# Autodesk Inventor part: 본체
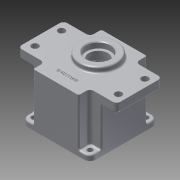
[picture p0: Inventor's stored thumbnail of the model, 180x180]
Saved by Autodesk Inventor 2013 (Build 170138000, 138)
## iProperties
Created: 2015-07
Part Number: 본체
Material: 알루미늄 6061
Document SubType Name: Modeling
Designer: user
Density: 2.71 g/cm^3
Mass: 706.146 g
Surface Area: 672.799 cm^2
Volume: 260.571 cm^3
Author: user
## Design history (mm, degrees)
sketch "스케치1"
  geometry: L1 (-65, -30)-(65, -30); L2 (65, -30)-(65, 30); L3 (65, 30)-(-65, 30); L4 (-65, 30)-(-65, -30); L5 (-65, -30)-(65, 30); L6 (65, -30)-(-65, 30); 1 further point
  constraints: 12 end point, 2 midpoint, 2 parallel, 1 horizontal, 1 perpendicular
  dimensions: "d0" = 130 distance of L3.end L2.end; "d1" = 60 distance of L2.end L1.end
extrude "돌출1" new body sketch "스케치1" distance "d2" = 12; taper "d3" = 0 deg
sketch "스케치2"
  geometry: L1 (-30, -45)-(30, -45); L2 (30, -45)-(30, 45); L3 (30, 45)-(-30, 45); L4 (-30, 45)-(-30, -45); L5 (-30, -45)-(30, 45); L6 (30, -45)-(-30, 45); 1 further point
  constraints: 12 end point, 2 midpoint, 2 parallel, 1 horizontal, 1 perpendicular
  dimensions: "d4" = 60 distance of L3.end L2.end; "d5" = 90 distance of L2.end L1.end
extrude "돌출2" join sketch "스케치2" distance "d6" = 70; taper "d7" = 0 deg
sketch "스케치3"
  geometry: L1 (-30, -45)-(30, -45) reference; L2 (30, -45)-(30, 45) reference; L3 (30, 45)-(-30, 45) reference; L4 (-30, 45)-(-30, -45) reference; L5 (-45, -45)-(45, -45); L6 (45, -45)-(45, 45); L7 (45, 45)-(-45, 45); L8 (-45, 45)-(-45, -45); L9 (-45, -45)-(45, 45); L10 (45, -45)-(-45, 45); 1 further point
  constraints: 12 end point, 2 midpoint, 2 parallel, 1 horizontal, 1 perpendicular
  dimensions: "d8" = 90 distance of L7.end L6.end; "d9" = 90 distance of L6.end L5.end
extrude "돌출3" join sketch "스케치3" distance "d10" = 7; taper "d11" = 0 deg
fillet "모깎기1" dims "d12" = 5
fillet "모깎기2" dims "d13" = 8
sketch "스케치4"
  geometry: L1 (-45, -30)-(45, -30); L2 (45, -30)-(45, 30); L3 (45, 30)-(-45, 30); L4 (-45, 30)-(-45, -30); L5 (-45, -30)-(45, 30); L6 (45, -30)-(-45, 30); 1 further point
  constraints: 12 end point, 2 midpoint, 2 parallel, 1 horizontal, 1 perpendicular
  dimensions: "d14" = 90 distance of L3.end L2.end; "d15" = 60 distance of L2.end L1.end
extrude "돌출4" join sketch "스케치4" distance "d16" = 70; taper "d17" = 0 deg
fillet "모깎기3" dims "d18" = 5
fillet "모깎기4" dims "d19" = 2
fillet "모깎기5" dims "d20" = 2
fillet "모깎기6" dims "d21" = 2
sketch "스케치5"
  geometry: L1 (-37, -37)-(37, -37); L2 (37, -37)-(37, 37); L3 (37, 37)-(-37, 37); L4 (-37, 37)-(-37, -37); L5 (-37, -37)-(37, 37); L6 (37, -37)-(-37, 37); C1 r 3.5 at (37, 37); C2 r 3.5 at (37, -37); C3 r 3.5 at (-37, 37); C4 r 3.5 at (-37, -37); 1 further point
  constraints: 12 end point, 4 centre point, 4 coincident, 2 midpoint, 2 parallel, 1 horizontal, 1 perpendicular
  dimensions: "d22" = 74 distance of L3.end L2.end; "d23" = 74 distance of L2.end L1.end; "d24" = 7 diameter of C1; "d25" = 7 diameter of C2; "d26" = 7 diameter of C3; "d27" = 7 diameter of C4
extrude "돌출5" cut sketch "스케치5" distance "d28" = 70; taper "d29" = 0 deg
sketch "스케치6"
  geometry: L1 (-55, -17.5)-(55, -17.5); L2 (55, -17.5)-(55, 17.5); L3 (55, 17.5)-(-55, 17.5); L4 (-55, 17.5)-(-55, -17.5); L5 (-55, -17.5)-(55, 17.5); L6 (55, -17.5)-(-55, 17.5); C1 r 4.5 at (55, 17.5); C2 r 4.5 at (55, -17.5); C3 r 4.5 at (-55, -17.5); C4 r 4.5 at (-55, 17.5); 1 further point
  constraints: 12 end point, 4 centre point, 4 coincident, 2 midpoint, 2 parallel, 1 horizontal, 1 perpendicular
  dimensions: "d30" = 110 distance of L3.end L2.end; "d31" = 35 distance of L2.end L1.end; "d32" = 9 diameter of C1; "d33" = 9 diameter of C2; "d34" = 9 diameter of C3; "d35" = 9 diameter of C4
extrude "돌출6" cut sketch "스케치6" distance "d36" = 20; taper "d37" = 0 deg
sketch "스케치7"
  geometry: C1 r 40 at (0, 0); 1 further point
  constraints: 1 centre point, 1 coincident
  dimensions: "d38" = 80 diameter of C1
extrude "돌출7" cut sketch "스케치7" distance "d39" = 9; taper "d40" = 0 deg
sketch "스케치8"
  geometry: C1 r 40 at (0, 0) reference; C2 r 39 at (0, 0)
  constraints: 1 centre point, 1 coincident
  dimensions: "d41" = 78 diameter of C2
extrude "돌출8" cut sketch "스케치8" distance "d42" = 52; taper "d43" = 0 deg
sketch "스케치10"
  geometry: L1 (-45, -70)-(-45, 0) reference; L2 (-45, 0)-(45, 0) reference; L3 (45, 0)-(45, -70) reference; L4 (45, -70)-(40, -70) reference; L5 (40, -70)-(40, -61) reference; L6 (40, -61)-(39, -61) reference; L7 (39, -61)-(39, -9) reference; L8 (39, -9)-(-39, -9) reference; L9 (-39, -9)-(-39, -61) reference; L10 (-39, -61)-(-40, -61) reference; L11 (-40, -61)-(-40, -70) reference; L12 (-40, -70)-(-45, -70) reference; L13 (0, 0)-(11, 0); L14 (0, 0)-(-20, 0); L15 (11, 0)-(11, -16); L16 (11, 0)-(11, 7); L17 (-20, 0)-(-20, -16); L18 (27, 7)-(36, 7); L19 (36, 7)-(36, -5); L20 (36, -5)-(31.5, -5); L21 (31.5, -5)-(31.5, -16); L22 (31.5, -16)-(28.5, -16); L23 (28.5, -16)-(28.5, -6); L24 (28.5, -6)-(23.5, -6); L25 (23.5, -6)-(23.5, -1); L26 (23.5, -1)-(27, -1); L27 (27, -1)-(27, 7); L28 (-20, -16)-(-6, -16); L29 (-6, -16)-(-6, 0); L30 (-6, 0)-(-20, 0)
  constraints: 36 end point, 7 parallel, 7 perpendicular, 3 point on line, 2 collinear
  dimensions: "d44" = 11 distance of L13.start L13.end; "d45" = 20 distance of L13.start L14.end; "d46" = 16 distance of L13.end L15.end; "d47" = 7 distance of L13.end L16.end; "d48" = 16 distance of L14.end L17.end; "d49" = 32 diameter of L27 L15; "d50" = 25 diameter of L25 L15; "d51" = 35 diameter of L23 L15; "d52" = 41 diameter of L21 L15; "d53" = 50 diameter of L19 L15; "d54" = 7 distance between parallel lines of L2 L18; "d55" = 7 distance between parallel lines of L8 L22; "d56" = 8 distance of L26.end L18.start; "d57" = 5 distance of L24.end L25.end; "d58" = 4 distance between parallel lines of L8 L20; "d59" = 14 distance of L17.end L28.end
  node "절단 모서리 투영1"
revolve "회전1" stored, may be unused: angle "d60" = 90 deg
revolve "회전2" stored, may be unused: angle "d61" = 90 deg
sketch "스케치11"
  geometry: C1 r 17.5 at (0, 0); C2 r 12.5 at (0, 0); A1 r 17.5 centre (0, 0) between (2.777, -17.278) and (-2.777, -17.278) reference; A2 r 14 centre (0, -31) between (2.777, -17.278) and (-2.777, -17.278) reference; A3 r 20.5 centre (0, 0) between (7.402, -19.117) and (-7.402, -19.117) reference; 1 further point
  constraints: 2 centre point, 2 coincident, 1 concentric
  dimensions: "d62" = 25 diameter of C2
extrude "돌출10" cut sketch "스케치11" distance "d65" = 10; taper "d66" = 0 deg
extrude "돌출11" cut sketch "스케치11" distance "d67" = 50; taper "d68" = 0 deg
fillet "모깎기7" dims "d69" = 2
chamfer "모따기1" distance "d70" = 1; stored, may be unused: second distance "d71" = 2, angle "d72" = 45 deg
hole "구멍1" diameter "d75" = 19; stored, may be unused: countersink angle "d79" = 90 deg, drill point angle "d81" = 0 deg; dims "d73" = 10, "d74" = 10, "d76" = 6, "d77" = 22, "d78" = 7, "d80" = 8
chamfer "모따기2" distance "d82" = 1; stored, may be unused: second distance "d83" = 2, angle "d84" = 45 deg
fillet "모깎기8" dims "d85" = 2
fillet "모깎기10" dims "d121" = 2, "d122" = 3
node "작업 평면2"
sketch "스케치12"
  geometry: L1 (45, 28)-(45, -28) reference; L2 (43, -30)-(35, -30) reference; L3 (30, -35)-(30, -43) reference; L4 (28, -45)-(-28, -45) reference; L5 (-30, -43)-(-30, -35) reference; L6 (-35, -30)-(-43, -30) reference; L7 (-45, -28)-(-45, 28) reference; L8 (-43, 30)-(-35, 30) reference; L9 (-30, 35)-(-30, 43) reference; L10 (-28, 45)-(28, 45) reference; L11 (30, 43)-(30, 35) reference; L12 (35, 30)-(43, 30) reference; L13 (0, 0)-(24.749, 24.749); L14 (0, 0)-(35, 0); L15 (24.603, 30.26)-(21.758, 27.415); L16 (30.26, 24.603)-(27.415, 21.758); L17 (5.657, 0)-(4.581, -1.076); C1 r 40 at (0, 0) reference; A1 r 39 centre (0, 0) between (30.26, 24.603) and (24.603, 30.26) reference; A2 r 2 centre (43, 28) between (45, 28) and (43, 30) reference; A3 r 2 centre (43, -28) between (43, -30) and (45, -28) reference; A4 r 5 centre (35, -35) between (35, -30) and (30, -35) reference; A5 r 2 centre (28, -43) between (28, -45) and (30, -43) reference; A6 r 2 centre (-28, -43) between (-30, -43) and (-28, -45) reference; A7 r 5 centre (-35, -35) between (-30, -35) and (-35, -30) reference; A8 r 2 centre (-43, -28) between (-45, -28) and (-43, -30) reference; A9 r 2 centre (-43, 28) between (-43, 30) and (-45, 28) reference; A10 r 5 centre (-35, 35) between (-35, 30) and (-30, 35) reference; A11 r 2 centre (-28, 43) between (-28, 45) and (-30, 43) reference; A12 r 2 centre (28, 43) between (30, 43) and (28, 45) reference; A13 r 5 centre (35, 35) between (30, 35) and (35, 30) reference; A14 r 35 centre (0, 0) between (24.749, 24.749) and (27.415, 21.758); A15 r 4 centre (24.749, 24.749) between (21.92, 27.577) and (27.577, 21.92); 2 further points
  constraints: 10 end point, 7 point on circle, 3 coincident, 3 point on line, 2 centre point, 2 parallel, 2 tangent, 1 equal length, 1 horizontal, 3 other
  dimensions: "d90" = 70 diameter of A14; "d91" = 45 deg angle of L14 L13; "d92" = 8 diameter of A15; "d95" = 4 distance from line of A1.centre L16
extrude "돌출12" join sketch "스케치12" distance "d96" = 55; taper "d97" = 0 deg
fillet "모깎기12" dims "d101" = 3.5
fillet "모깎기13" dims "d105" = 2
hole "구멍2" diameter "d108" = 3.459; stored, may be unused: countersink angle "d112" = 90 deg, drill point angle "d114" = 118 deg; dims "d106" = 10, "d107" = 10, "d109" = 12, "d110" = 22, "d111" = 7, "d113" = 15
sketch "스케치13"
  geometry: L1 (-28, -45)-(28, -45) reference; L2 (-30, -35)-(-30, -43) reference; L3 (0, -45)-(0, -30); 2 further points
  constraints: 2 end point, 1 coincident, 1 midpoint, 1 parallel, 1 other
  dimensions: "d118" = 15 distance of L3.start L3.end
feature "엠보싱1" sketch "스케치13" dims "d119" = 0.5, "d120" = 0
node "작업 평면3"
sketch "스케치14"
  geometry: C1 r 15.7 at (0, 0) reference; C2 r 16 at (0, 0); 1 further point
  constraints: 1 centre point, 1 coincident
  dimensions: "d123" = 32 diameter of C2
extrude "돌출13" cut sketch "스케치14" distance "d124" = 1; taper "d125" = 0 deg
sketch "스케치15"
  geometry: C1 r 15.7 at (0, 0) reference; C2 r 12.5 at (0, 0) reference; C3 r 16 at (0, 0); 1 further point
  constraints: 1 centre point, 1 coincident
  dimensions: "d126" = 32 diameter of C3
extrude "돌출14" cut sketch "스케치15" distance "d127" = 1; taper "d128" = 0 deg
fillet "모깎기14" dims "d129" = 0.3
node "솔리드1"
pattern_circular "원형 패턴1" dims angle "d99" = 360 deg
pattern_circular "원형 패턴2" dims angle "d103" = 360 deg
pattern_circular "원형 패턴3" dims angle "d116" = 360 deg
node "절단 모서리 투영2"
other parameters: "d89" = -9, "d93" = 4, "d94" = 8
